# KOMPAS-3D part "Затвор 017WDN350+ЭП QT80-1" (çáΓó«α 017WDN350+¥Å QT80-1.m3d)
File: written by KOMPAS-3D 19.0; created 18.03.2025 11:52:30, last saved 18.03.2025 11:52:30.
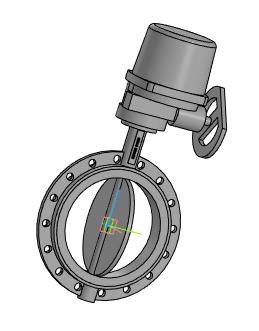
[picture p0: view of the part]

Document properties: Полное имя файла: Затвор 017WDN350+ЭП QT80-1.a3d

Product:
- Part/product: Затвор 017WDN350+ЭП QT80-1
    Масса: 180.045

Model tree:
1. Операция без истории:1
